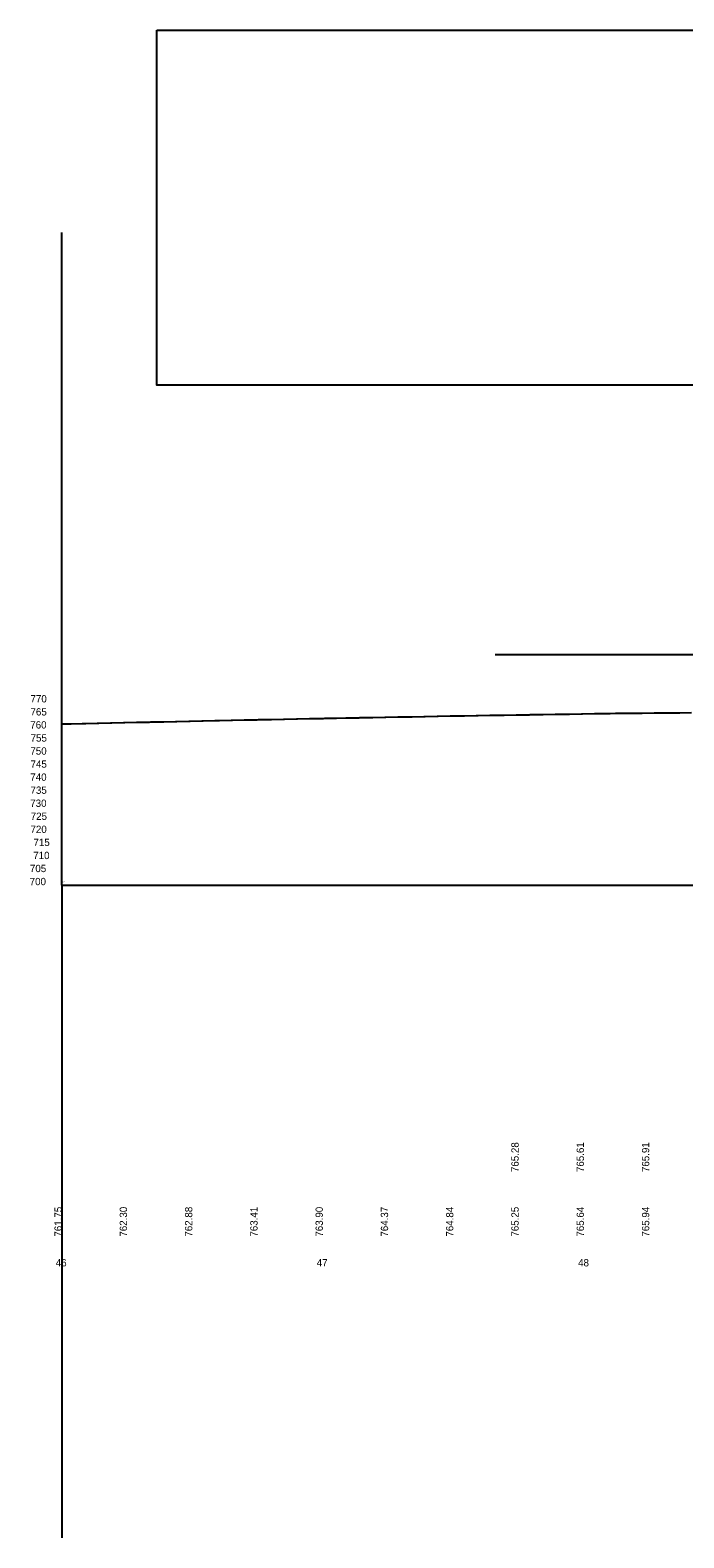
# Model space of a CAD drawing. Extents: x 40 to 3352, y -2509 to 347.
# Drawn here: x 40 to 291, y -230 to 347 of the extents above; entities that cross this region are included whole.
import ezdxf

# ---------------------------------------------------------------- set-up
doc = ezdxf.new("R2010")
doc.units = 0
for name, color, linetype in [('Default', 7, 'Continuous'), ('GK_Cells', 7, 'Continuous'), ('PF_P_Sta_Elev_Text', 7, 'Continuous'), ('PF_P_Text', 7, 'Continuous'), ('PF_X_Ground_Line', 7, 'Continuous'), ('PF_X_Text', 7, 'Continuous')]:
    doc.layers.add(name, color=color, linetype=linetype)

msp = doc.modelspace()

# ---------------------------------------------------------------- linework, layer by layer
at = {"layer": 'Default'}
msp.add_lwpolyline([(88.85, 347.26), (976.56, 347.26), (976.56, 211.32), (88.85, 211.32)], close=True, dxfattribs=at)
at = {"layer": 'GK_Cells'}
for q in [(52.41, 269.74), (3352.42, 19.74), (52.41, -230.26)]:
    msp.add_line((52.41, 19.74), q, dxfattribs=at)
at = {"layer": 'PF_P_Text'}
msp.add_line((218.41, 108.13), (784.41, 108.13), dxfattribs=at)
at = {"layer": 'PF_X_Ground_Line'}
for points in [[(52.41, 81.49), (54.77, 81.54), (55.98, 81.57), (60.26, 81.66), (61.02, 81.67), (61.59, 81.68), (66.02, 81.78), (66.59, 81.79), (71.02, 81.9), (71.57, 81.91), (76.02, 82.01), (76.56, 82.02), (81.02, 82.13), (81.56, 82.14), (86.02, 82.24), (86.56, 82.25), (91.02, 82.36), (91.55, 82.37), (96.02, 82.47)], [(96.02, 82.47), (96.55, 82.48), (101.02, 82.59), (101.53, 82.6), (106.02, 82.7), (106.53, 82.71), (111.02, 82.82), (111.16, 82.82), (112.28, 82.85), (112.8, 82.86), (117.28, 82.95), (117.78, 82.96), (122.28, 83.04), (122.77, 83.06), (127.28, 83.14), (127.77, 83.15), (132.28, 83.24), (132.76, 83.25), (137.28, 83.34), (137.74, 83.35), (142.28, 83.44), (142.73, 83.45), (147.28, 83.54), (147.73, 83.55), (152.28, 83.64), (152.72, 83.65), (153.16, 83.66), (157.64, 83.75), (161.19, 83.82), (165.69, 83.9), (166.15, 83.9), (166.57, 83.91), (171.15, 84), (171.57, 84), (176.14, 84.09), (176.59, 84.1), (181.14, 84.18), (181.59, 84.19), (186.14, 84.27), (186.6, 84.28), (191.14, 84.37), (191.6, 84.37), (196.14, 84.46), (196.6, 84.47), (201.14, 84.55), (201.6, 84.56), (206.14, 84.64), (206.61, 84.65), (211.13, 84.74), (211.31, 84.74), (211.86, 84.75), (216.39, 84.82), (216.86, 84.83), (221.39, 84.9), (221.86, 84.9), (226.39, 84.98), (226.86, 84.98), (231.4, 85.05), (231.85, 85.06), (236.41, 85.13), (236.85, 85.14), (241.41, 85.21), (241.85, 85.21), (246.43, 85.28), (246.85, 85.29), (251.44, 85.36), (251.85, 85.37), (256.44, 85.44), (256.85, 85.44), (258.61, 85.49), (262.49, 85.55), (264.45, 85.58), (268.38, 85.62), (272.32, 85.65), (274.32, 85.65), (274.7, 85.66), (279.32, 85.7), (280.22, 85.72), (284.93, 85.79), (285.73, 85.8), (286.56, 85.81), (289.14, 85.8), (293.61, 85.84)]]:
    msp.add_lwpolyline(points, dxfattribs=at)

# ---------------------------------------------------------------- texts
at = {"layer": 'GK_Cells'}
for s, p in [('450', (52.41, 21.21)), ('WINCHESTER', (52.41, 21)), ('4600.000000', (52.41, 20.79)), ('700', (52.41, 20.58)), ('1', (52.41, 20.37)), ('1', (52.41, 20.16)), ('NOGAP', (52.41, 19.95))]:
    msp.add_text(s, height=0.14, dxfattribs=at).set_placement(p)
at = {"layer": 'PF_P_Sta_Elev_Text'}
for s, p in [('770', (40.43, 89.74)), ('770', (40.43, 89.74)), ('765', (40.43, 84.74)), ('765', (40.43, 84.74)), ('760', (40.34, 79.74)), ('760', (40.34, 79.74)), ('755', (40.47, 74.74)), ('755', (40.47, 74.74)), ('750', (40.38, 69.74)), ('750', (40.38, 69.74)), ('745', (40.45, 64.74)), ('745', (40.45, 64.74)), ('740', (40.36, 59.74)), ('740', (40.36, 59.74)), ('730', (40.34, 49.74)), ('730', (40.34, 49.74)), ('735', (40.43, 54.74)), ('735', (40.43, 54.74)), ('725', (40.51, 44.74)), ('725', (40.51, 44.74)), ('720', (40.43, 39.74)), ('720', (40.43, 39.74)), ('715', (41.57, 34.74)), ('715', (41.57, 34.74)), ('710', (41.49, 29.74)), ('710', (41.49, 29.74)), ('705', (40.21, 24.74)), ('705', (40.21, 24.74)), ('700', (40.12, 19.74)), ('700', (40.12, 19.74)), ('46', (50.11, -126.29)), ('47', (150.06, -126.29)), ('48', (250.18, -126.29))]:
    msp.add_text(s, height=2.8, dxfattribs=at).set_placement(p)
at = {"layer": 'PF_P_Text'}
for s, p in [('765.28', (227.41, -90.16)), ('765.61', (252.41, -90.16)), ('765.91', (277.42, -90.16))]:
    msp.add_text(s, height=2.8, rotation=90, dxfattribs=at).set_placement(p)
at = {"layer": 'PF_X_Text'}
for s, p in [('761.75', (52.41, -114.89)), ('762.30', (77.41, -114.89)), ('762.88', (102.41, -114.89)), ('763.41', (127.41, -114.89)), ('763.90', (152.41, -114.89)), ('764.37', (177.41, -114.89)), ('764.84', (202.41, -114.89)), ('765.25', (227.41, -114.89)), ('765.64', (252.41, -114.89)), ('765.94', (277.42, -114.89))]:
    msp.add_text(s, height=2.8, rotation=90, dxfattribs=at).set_placement(p)

doc.saveas('drawing.dxf')
